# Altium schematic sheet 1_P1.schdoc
size 307 x 218 mm; Symbol: Drawing-Symbol_A4; Device: Drawing-Symbol_A4; Company: 嘉立创EDA; Version: V1.0; Page Size: A4; @Project Name: HDMI2CSI; @Page Count: 1; @Update Date: 2025-12-07; @Create Date: 2025-08-24; @Schematic Name: HDMI2CSI2_1; @Page No: 1; @Page Name: P1; @Create Time: 00:54:53; @Update Time: 19:15:54; Width: 1170; Height: 825; Region Start: 1; X Region Count: 6; Y Region Count: 4; Blade Width: 10; Title Block Position: 3; @Board Name: HDMI_2_CSI_SE
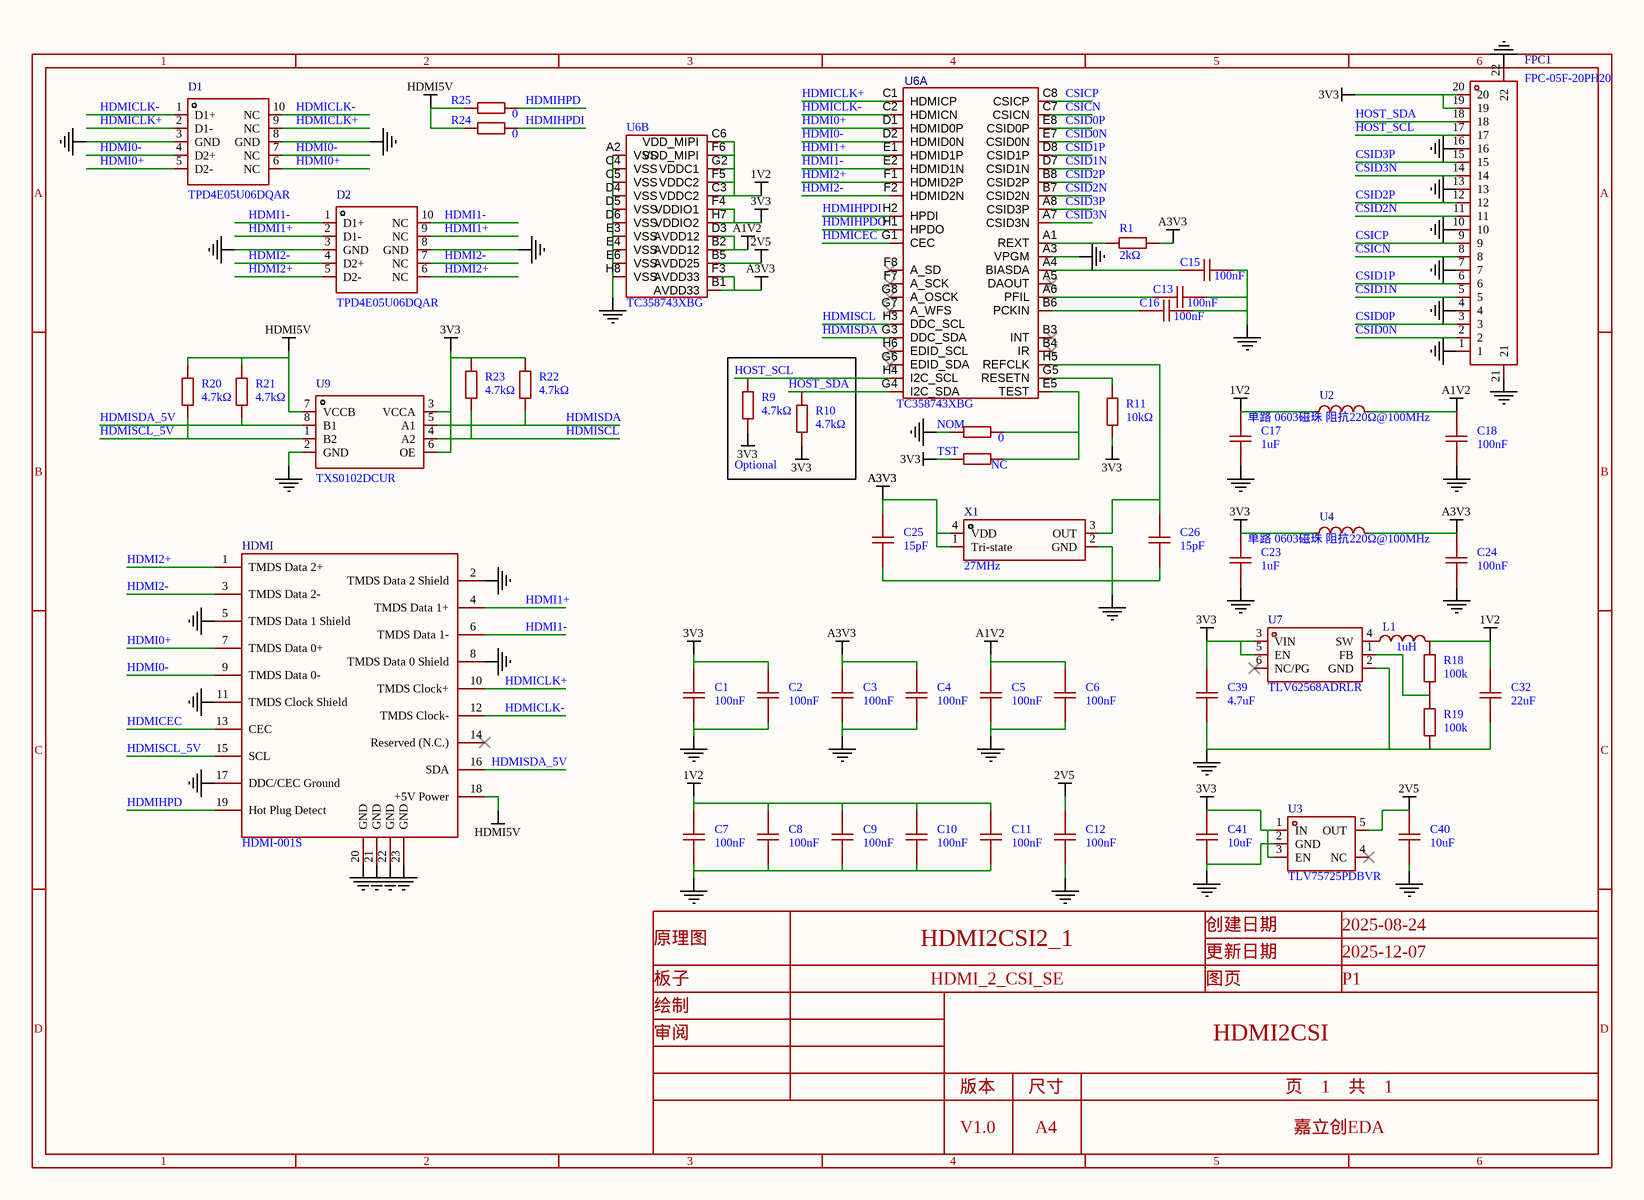
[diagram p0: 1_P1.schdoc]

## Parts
C1  100nF  [C0603]
C2  100nF  [C0603]
C3  100nF  [C0603]
C4  100nF  [C0603]
C5  100nF  [C0603]
C6  100nF  [C0603]
C7  100nF  [C0603]
C8  100nF  [C0603]
C9  100nF  [C0603]
C10  100nF  [C0603]
C11  100nF  [C0603]
C12  100nF  [C0603]
C13  100nF  [C0603]
C15  100nF  [C0603]
C16  100nF  [C0603]
C17  1uF  [C0603]
C18  100nF  [C0603]
C23  1uF  [C0603]
C24  100nF  [C0603]
C25  15pF  [C0603]
C26  15pF  [C0603]
C32  22uF  [C0805]
C39  4.7uF  [C0603]
C40  10uF  [C0603]
C41  10uF  [C0603]
D1  TPD4E05U06DQAR  [USON-10_L2.5-W1.0-P0.50-BL]
D2  TPD4E05U06DQAR  [USON-10_L2.5-W1.0-P0.50-BL]
FPC1  FPC-05F-20PH20  [FPC-SMD_20P-P0.50_XUNPU_FPC-05F-20PH20]
HDMI  HDMI-001S  [HDMI-SMD_HDMI-001S]
L1  1uH  [IND-SMD_L2.5-W2.0_WPN252012H]
NOM  0  [R0603]
R1  2kΩ  [R0603]
R9  4.7kΩ  [R0603]
R10  4.7kΩ  [R0603]
R11  10kΩ  [R0603]
R18  100k  [R0603]
R19  100k  [R0603]
R20  4.7kΩ  [R0603]
R21  4.7kΩ  [R0603]
R22  4.7kΩ  [R0603]
R23  4.7kΩ  [R0603]
R24  0  [R0603]
R25  0  [R0603]
TST  NC  [R0603]
U2  LCSC Part Name: 单路 0603磁珠 阻抗220Ω@100MHz  [L0603]  (hidden comment: BLM18EG221SN1D)
U3  TLV75725PDBVR  [SOT-23-5_L2.9-W1.6-P0.95-LS2.8-BR]
U4  LCSC Part Name: 单路 0603磁珠 阻抗220Ω@100MHz  [L0603]  (hidden comment: BLM18EG221SN1D)
U6  TC358743XBG  [BGA-64_L6.0-W6.0-W8-R8-P0.65-D0.40-TL]  (parts A,B of 2)
U7  TLV62568ADRLR  [SOT-563_L1.6-W1.2-P0.50-LS1.6-BL]
U9  TXS0102DCUR  [VSON8_L2.0-W2.3-P0.50-LS3.1-BL]
X1  27MHz  [OSC-SMD_4P-L3.2-W2.5-BL]

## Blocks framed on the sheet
Optional: R9 R10

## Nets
1V2: C7.2 C8.2 C9.2 C10.2 C11.2 C17.2 C32.2 L1.2 R18.2 U2.1 U6.C3(VDDC2) U6.C6(VDD_MIPI) U6.F5(VDDC2) U6.F6(VDD_MIPI) U6.G2(VDDC1)
2V5: C12.2 C40.2 U3.5(OUT) U6.B5(AVDD25)
3V3: C1.2 C2.2 C23.2 C39.2 C41.2 FPC1.19 FPC1.20 R9.1 R10.1 R11.1 R22.1 R23.1 TST.1 U3.1(IN) U3.3(EN) U4.1 U6.F4(VDDIO1) U6.H7(VDDIO2) U7.3(VIN) U7.5(EN) U9.3(VCCA) U9.6(OE)
A1V2: C5.2 C6.2 C18.2 U2.2 U6.B2(AVDD12) U6.D3(AVDD12)
A3V3: C3.2 C4.2 C24.2 C25.2 R1.2 U4.2 U6.B1(AVDD33) U6.F3(AVDD33) X1.1(Tri-state) X1.4(VDD)
GND: C1.1 C2.1 C3.1 C4.1 C5.1 C6.1 C7.1 C8.1 C9.1 C10.1 C11.1 C12.1 C13.2 C15.2 C16.2 C17.1 C18.1 C23.1 C24.1 C25.1 C26.1 C32.1 C39.1 C40.1 C41.1 D1.3(GND) D1.8(GND) D2.3(GND) D2.8(GND) FPC1.1 FPC1.4 FPC1.7 FPC1.10 FPC1.13 FPC1.16 FPC1.21 FPC1.22 HDMI.2(TMDS_Data_2_Shield) HDMI.5(TMDS_Data_1_Shield) HDMI.8(TMDS_Data_0_Shield) HDMI.11(TMDS_Clock_Shield) HDMI.17(DDC/CEC_Ground) HDMI.20(GND) HDMI.21(GND) HDMI.22(GND) HDMI.23(GND) NOM.2 R19.1 U3.2(GND) U6.A2(VSS) U6.A3(VPGM) U6.C4(VSS) U6.C5(VSS) U6.D4(VSS) U6.D5(VSS) U6.D6(VSS) U6.E3(VSS) U6.E4(VSS) U6.E6(VSS) U6.H8(VSS) U7.2(GND) U9.2(GND) X1.2(GND)
HDMI5V: HDMI.18(+5V_Power) R20.2 R21.2 R24.2 R25.2 U9.7(VCCB)
CSICN: FPC1.8 U6.C7(CSICN)
CSICP: FPC1.9 U6.C8(CSICP)
CSID0N: FPC1.2 U6.E7(CSID0N)
CSID0P: FPC1.3 U6.E8(CSID0P)
CSID1N: FPC1.5 U6.D7(CSID1N)
CSID1P: FPC1.6 U6.D8(CSID1P)
CSID2N: FPC1.11 U6.B7(CSID2N)
CSID2P: FPC1.12 U6.B8(CSID2P)
CSID3N: FPC1.14 U6.A7(CSID3N)
CSID3P: FPC1.15 U6.A8(CSID3P)
HDMI0+: D1.5(D2-) D1.6(NC) HDMI.7(TMDS_Data_0+) U6.D1(HDMID0P)
HDMI0-: D1.4(D2+) D1.7(NC) HDMI.9(TMDS_Data_0-) U6.D2(HDMID0N)
HDMI1+: D2.2(D1-) D2.9(NC) HDMI.4(TMDS_Data_1+) U6.E1(HDMID1P)
HDMI1-: D2.1(D1+) D2.10(NC) HDMI.6(TMDS_Data_1-) U6.E2(HDMID1N)
HDMI2+: D2.5(D2-) D2.6(NC) HDMI.1(TMDS_Data_2+) U6.F1(HDMID2P)
HDMI2-: D2.4(D2+) D2.7(NC) HDMI.3(TMDS_Data_2-) U6.F2(HDMID2N)
HDMICEC: HDMI.13(CEC) U6.G1(CEC)
HDMICLK+: D1.2(D1-) D1.9(NC) HDMI.10(TMDS_Clock+) U6.C1(HDMICP)
HDMICLK-: D1.1(D1+) D1.10(NC) HDMI.12(TMDS_Clock-) U6.C2(HDMICN)
HDMIHPD: HDMI.19(Hot_Plug_Detect) R25.1
HDMIHPDI: R24.1 U6.H2(HPDI)
HDMIHPDO: U6.H1(HPDO)
HDMISCL: R23.2 U6.H3(DDC_SCL) U9.4(A2)
HDMISCL_5V: HDMI.15(SCL) R20.1 U9.1(B2)
HDMISDA: R22.2 U6.G3(DDC_SDA) U9.5(A1)
HDMISDA_5V: HDMI.16(SDA) R21.1 U9.8(B1)
HOST_SCL: FPC1.17 R9.2 U6.H4(I2C_SCL)
HOST_SDA: FPC1.18 R10.2 U6.G4(I2C_SDA)
NetC13_1: C13.1 U6.A6(PFIL)
NetC15_1: C15.1 U6.A4(BIASDA)
NetC16_1: C16.1 U6.B6(PCKIN)
NetC26_2: C26.2 U6.H5(REFCLK) X1.3(OUT)
NetL1_1: L1.1 U7.4(SW)
NetNOM_1: NOM.1 TST.2 U6.E5(TEST)
NetR1_1: R1.1 U6.A1(REXT)
NetR11_2: R11.2 U6.G5(RESETN)
NetR18_1: R18.1 R19.2 U7.1(FB)

Not connected (* = marked no-connect by the designer): HDMI 14(Reserved_(N.C.))*; U3 4(NC)*; U6 A5(DAOUT)* B3(INT)* B4(IR)* F7(A_SCK)* F8(A_SD)* G6(EDID_SDA)* G7(A_WFS)* G8(A_OSCK)* H6(EDID_SCL)*; U7 6(NC/PG)*

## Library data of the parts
C1-C13 C15 C16 C18 C24 C25 = CGA0603X7R104K500JT: Manufacturer: HRE(芯声); Symbol: Capacitance; Add into BOM: yes; Tolerance: ±10%; Voltage Rating: 50V; Temperature Coefficient: X7R
C17 C23 C39-C41 = CL10A105KB8NNNC: Manufacturer: SAMSUNG(三星); Symbol: Capacitance; Add into BOM: yes; Tolerance: ±10%; Voltage Rated: 50V; Temperature Coefficient: X5R
C26 = CL10C150JB8NNNC: Manufacturer: SAMSUNG(三星); Symbol: Capacitance; Add into BOM: yes; Tolerance: ±5%; Voltage Rated: 50V; Temperature Coefficient: C0G
C32 = CL21A226MAQNNNE: Manufacturer: SAMSUNG(三星); Symbol: Capacitance; Add into BOM: yes; Tolerance: ±20%; Voltage Rated: 25V; Temperature Coefficient: X5R
D1 D2 = TPD4E05U06DQAR_C138714: Manufacturer: TI(德州仪器); Add into BOM: yes; Polarity: 单向; Reverse Stand-Off Voltage (Vrwm): 5.5V; Clamping Voltage: 14V; Peak Pulse Current (Ipp): 2.5A@8/20us; Peak Pulse Power Dissipation (Ppp): 40W@8/20us; Voltage - Breakdown: 6.5V; Reverse Leakage Current (Ir): 10nA; Number of Channels: 四路; level of protection: IEC 61000-4-4；IEC 61000-4-5；IEC 61000-4-2; Type: TVS; Junction Capacitance: 0.5pF
FPC1 = FPC-05F-20PH20: Manufacturer: XUNPU(讯普); Add into BOM: yes; Locking Feature: 翻盖式; Number of Contacts: 20P; Pitch: 0.5mm; FFC, FCB Thickness: 0.3mm; Rated Voltage (Max): 50V; Current Rating (Max): 500mA
HDMI = HDMI-001S: Manufacturer: XUNPU(讯普); Add into BOM: yes; Connector Type: HDMI-A; Gender: 母
L1 = WPN252012H1R0MT: Manufacturer: Sunlord(顺络); Symbol: SDFL1608S100KTF; Add into BOM: yes; Tolerance: ±20%; Current Rating: 3A; Current - Saturation(Isat): 4.2A; DC Resistance(DCR): 54mΩ
NOM R11 R24 R25 TST = 0603WAF1002T5E: Manufacturer: UNI-ROYAL(厚声); Symbol: 电阻; Add into BOM: yes; Tolerance: ±1%; Power(Watts): 100mW; Voltage-Supply(Max): 75V; Temperature Coefficient: ±100ppm/℃
R1 = 0603WAF2001T5E: Manufacturer: UNI-ROYAL(厚声); Symbol: 电阻; Add into BOM: yes; Tolerance: ±1%; Power(Watts): 100mW; Voltage-Supply(Max): 75V; Temperature Coefficient: ±100ppm/℃
R9 R10 = 0603WAF4701T5E: Manufacturer: UNI-ROYAL(厚声); Symbol: 电阻; Add into BOM: yes; Tolerance: ±1%; Power(Watts): 100mW; Overload Voltage (Max): 75V; Temperature Coefficient: ±100ppm/℃
R18 R19 = Res_0603: Symbol: 电阻; Convert to PCB: yes
R20-R23 = 0603WAF4702T5E: Manufacturer: UNI-ROYAL(厚声); Symbol: 0402WGF4702TCE; Add into BOM: yes; Tolerance: ±1%; Power(Watts): 100mW; Voltage-Supply(Max): 75V; Temperature Coefficient: ±100ppm/℃
U2 U4 = BLM18EG221SN1D: Manufacturer: muRata(村田); Symbol: BLM18PG121SN1D_C14709; Add into BOM: yes; Impedance @ Frequency: 220Ω@100MHz; Tolerance: ±25%; DC Resistance: 50mΩ; Current Rating: 2A; Circuits: 1
U3 = TLV75725PDBVR: Manufacturer: TI(德州仪器); Add into BOM: yes; Output Type: 固定; Maximum Input Voltage: 5.5V; Output Voltage: 2.5V; Output Current: 1A; Dropout Voltage: 650mV@(1A); Output Polarity: 正极; Number of Outputs: 1
U6 = TC358743XBG: Add into BOM: yes
U7 = TLV62568ADRLR: Manufacturer: TI(德州仪器); Add into BOM: yes; Function: 降压型; Output Type: 可调; Voltage - Supply: 2.5V~5.5V; Output Voltage: 600mV~5.5V; Output Current: 1A; Frequency - Switching: 1.5MHz; Synchronous Rectifier: 是; Number of Outputs: 1; Topology: 降压式; Switch tube (built-in/external): 内置
U9 = TXS0102DCUR: Manufacturer: TI(德州仪器); Add into BOM: yes; Channel Type: 双向; Data Rate: 24Mbps; Voltage - Supply(VCCA): 1.65V~3.6V; Voltage - Supply(VCCB): 2.3V~5.5V; Number of Circuits: 2; Output Type: 开漏；推挽式
X1 = OT2EL4C4JI-111OLP-27M: Manufacturer: YXC(扬兴晶振); Add into BOM: yes; Normal temperature Frequency Tolerance: ±10ppm; Output Type: CMOS; Voltage - Supply: 1.8V~3.3V; Frequency Stability: ±20ppm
